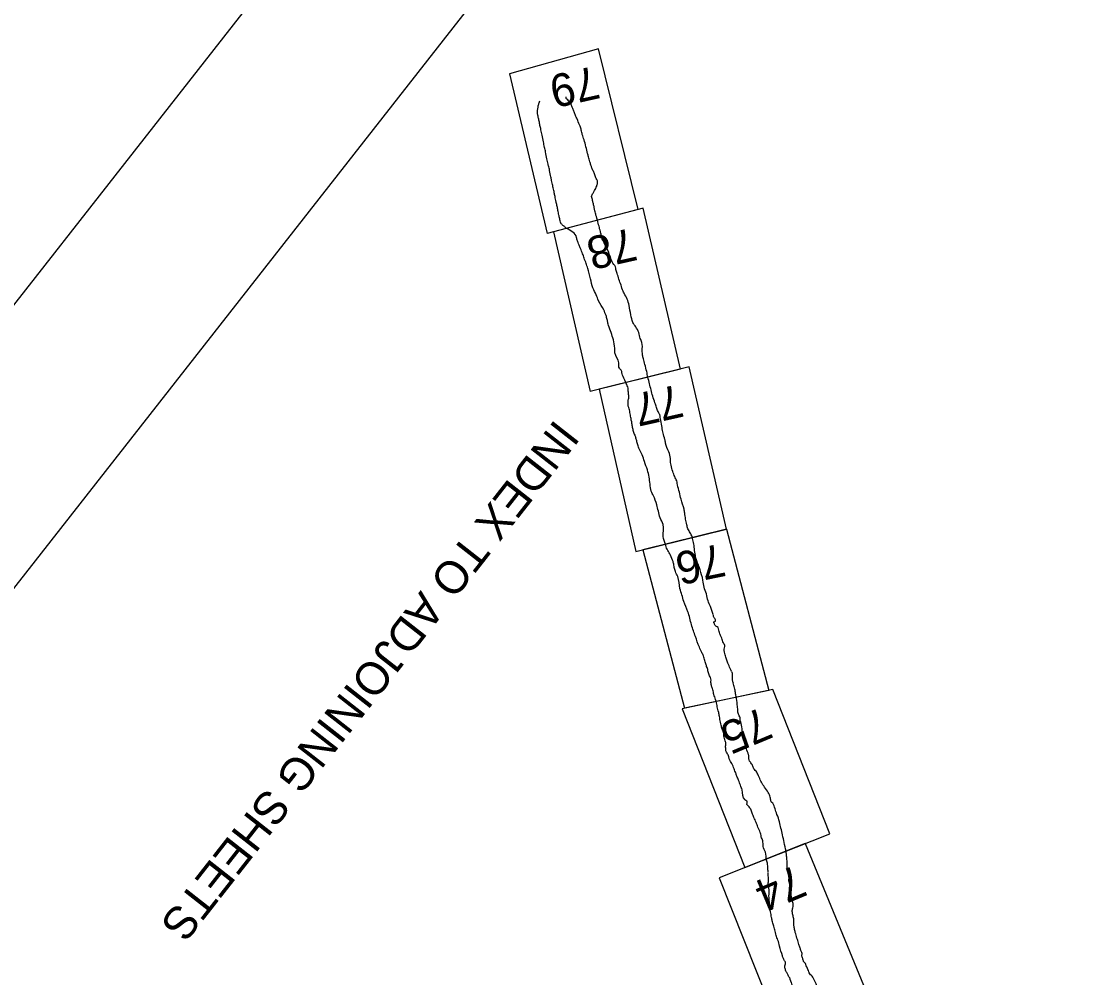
# Model space of a CAD drawing. Extents: x 3896831 to 3918110, y 171006 to 193349.
# Drawn here: x 3900688 to 3902596, y 182098 to 183807 of the extents above; entities that cross this region are included whole.
import ezdxf

# ---------------------------------------------------------------- set-up
doc = ezdxf.new("R2010")
doc.units = 0
for name, color, linetype in [('G-ANNO-NPLT', 7, 'Continuous'), ('V-ANNO-NPLT', 7, 'Continuous'), ('V-ANNO-SYMB', 7, 'Continuous')]:
    doc.layers.add(name, color=color, linetype=linetype)

msp = doc.modelspace()

# ---------------------------------------------------------------- linework, layer by layer
at = {"layer": 'G-ANNO-NPLT'}
msp.add_lwpolyline([(3908370.1, 193119.4), (3897060.8, 178689.9), (3906571.2, 171236.1), (3917880.5, 185665.6)], close=True, dxfattribs=at)
at = {"layer": 'V-ANNO-NPLT'}
msp.add_line((3901791, 183470.5), (3901628.5, 183427.7), dxfattribs=at)
for points in [[(3901791, 183470.5), (3901720.2, 183757.6), (3901560.9, 183713), (3901628.5, 183427.7)], [(3901866.5, 183185.2), (3901800.1, 183472.9), (3901639.4, 183430.6)], [(3901639.4, 183430.6), (3901705.1, 183145.5)], [(3901882, 183189), (3901721, 183149.4), (3901786.9, 182859.3)], [(3901948.7, 182899), (3901882, 183189)], [(3901866.5, 183185.2), (3901705.1, 183145.5)], [(3901786.9, 182859.3), (3901948.7, 182899)], [(3901948.7, 182899), (3901799.4, 182862.4)], [(3901948.7, 182899), (3902024.5, 182611)], [(3901799.4, 182862.4), (3901873.5, 182578.9)], [(3902031.6, 182612.5), (3901869.7, 182578.1), (3901981.7, 182294.3)], [(3902024.5, 182611), (3901873.5, 182578.9)], [(3902133.5, 182354.4), (3902031.6, 182612.5)], [(3901981.7, 182294.3), (3902133.5, 182354.4)], [(3902089.5, 182337), (3901935.6, 182276.1), (3902045.9, 181998.7)], [(3902089.5, 182337), (3902202.4, 182063.9)]]:
    msp.add_lwpolyline(points, dxfattribs=at)
for points in [[(3901617.1, 183613.2), (3901615.4, 183620.7), (3901613.9, 183628.3), (3901612.4, 183635.2), (3901611.8, 183639.4), (3901610.9, 183644.6), (3901611.6, 183650.3), (3901612.4, 183656), (3901613.9, 183661.2), (3901615, 183664.6)], [(3901685.9, 183621.8), (3901681.7, 183632.4), (3901678.9, 183638.5), (3901676.3, 183644.8), (3901674.1, 183650.8), (3901671.6, 183656.6), (3901669.8, 183661.4), (3901668.7, 183662.5), (3901666.5, 183664.7), (3901663.3, 183667.9), (3901662.4, 183668.9), (3901662, 183670.1), (3901662.1, 183671.9)], [(3901629.8, 183551.3), (3901627.8, 183561.1), (3901625.5, 183573.3), (3901623.7, 183581.6), (3901621.5, 183591.4), (3901619.1, 183603.5), (3901617.1, 183613.2)], [(3901700.5, 183570.7), (3901697.6, 183582.7), (3901694.2, 183595.1), (3901691.1, 183604.7), (3901689.2, 183612.2), (3901687.1, 183619.6), (3901685.9, 183621.8)], [(3901716.9, 183512.4), (3901718.3, 183517.7), (3901718.3, 183520.4), (3901716.1, 183525.7), (3901713.2, 183532.6), (3901710.8, 183538.9), (3901708.2, 183545), (3901706.4, 183549.9), (3901704.7, 183555.8), (3901702.1, 183564.8), (3901700.5, 183570.7)], [(3901644.5, 183483.9), (3901642.3, 183493.8), (3901640.9, 183500.3), (3901639.2, 183509.2), (3901637.1, 183517.4), (3901636.3, 183522.3), (3901635, 183528.7), (3901632.7, 183540.2), (3901630.5, 183548.8), (3901629.8, 183551.3)], [(3901718, 183451.5), (3901716.9, 183455.3), (3901715.5, 183460.4), (3901714.7, 183464), (3901713.5, 183468.4), (3901712.5, 183473.8), (3901710.8, 183480.9), (3901709.5, 183486.5), (3901708.7, 183490.3), (3901707.8, 183493.8), (3901710.5, 183499.9), (3901713, 183504.6), (3901715, 183508), (3901716.9, 183512.4)], [(3901662.5, 183437), (3901658.4, 183440.5), (3901654.3, 183444), (3901652.7, 183446.3), (3901650.7, 183454.1), (3901649.1, 183460.5), (3901647.5, 183469), (3901646.1, 183475.8), (3901644.6, 183483.2), (3901644.5, 183483.9)], [(3901691.7, 183391.4), (3901687.9, 183400.8), (3901685.2, 183406.8), (3901683.8, 183411.4), (3901681.4, 183417.5), (3901680.8, 183420.4), (3901662.5, 183437)], [(3901723.4, 183430.9), (3901722.1, 183435.7), (3901721, 183440.5), (3901718, 183451.5)], [(3901774.6, 183299), (3901771.5, 183310.4), (3901765.7, 183320.8), (3901763.9, 183324.4), (3901760.3, 183335.5), (3901756.6, 183345.9), (3901753.4, 183356.3), (3901751.2, 183363.3), (3901750.5, 183368.2), (3901747.4, 183372.4), (3901738.3, 183393.7), (3901729.9, 183410.8), (3901726, 183420.2), (3901725, 183424.9), (3901723.4, 183430.9)], [(3901733.6, 183281.1), (3901729.3, 183291), (3901720.2, 183307.5), (3901716, 183317.8), (3901710.2, 183330.4), (3901705.9, 183346.4), (3901700.8, 183365.3), (3901698, 183374.1), (3901694.4, 183383.5), (3901691.7, 183391.4)], [(3901806.3, 183180.7), (3901803, 183193.4), (3901800.2, 183203.7), (3901798.8, 183210.2), (3901798.3, 183217.8), (3901797.5, 183232.7), (3901794.8, 183239.8), (3901791.9, 183250.6), (3901786.7, 183260.6), (3901781.7, 183268.7), (3901777.8, 183282.1), (3901774.6, 183299)], [(3901769.6, 183159.4), (3901764.1, 183171.9), (3901762.2, 183176.6), (3901761.1, 183182.4), (3901757.4, 183186.7), (3901756.2, 183196.2), (3901749.4, 183214.2), (3901749, 183222.6), (3901746.7, 183237.8), (3901738.2, 183263.1), (3901737, 183267.6), (3901735.6, 183273.6), (3901733.6, 183281.1)], [(3901829.5, 183104), (3901826.5, 183109.6), (3901823.8, 183116.7), (3901821, 183124.8), (3901817, 183136.9), (3901811.3, 183159), (3901808.3, 183170.8), (3901806.3, 183180.9)], [(3901723, 183149.9), (3901722.8, 183149.5), (3901722.2, 183149.2), (3901721.8, 183149), (3901721.2, 183148.7)], [(3901778.8, 183092), (3901778.7, 183093.1), (3901777.4, 183100.9), (3901775.9, 183110.1), (3901775, 183114.4), (3901773.1, 183118.7), (3901773.1, 183125.8), (3901773.1, 183130.2), (3901774, 183133), (3901773.8, 183139.9), (3901773.4, 183144.3), (3901772.9, 183151.4), (3901769.6, 183159.4)], [(3901778.8, 183092), (3901779.7, 183085.1), (3901781.2, 183077.9), (3901783.3, 183071), (3901786.6, 183063.2)], [(3901887.5, 182885.2), (3901884, 182892.6), (3901880, 182899.5), (3901878, 182907.1), (3901875.8, 182917), (3901874.3, 182927.9), (3901873.1, 182934.7), (3901867.6, 182952.5), (3901864.7, 182965.2), (3901861.3, 182978.3), (3901859.1, 182987.5), (3901855.5, 182994.8), (3901852, 183005.1), (3901849.2, 183016.2), (3901848.7, 183025.5), (3901845.8, 183037.4), (3901839.8, 183052.7), (3901839.3, 183056.7), (3901838.6, 183059.5), (3901835.4, 183071), (3901833.6, 183080.6), (3901831.5, 183093.4), (3901829.5, 183104)], [(3901790.3, 183050.1), (3901788.3, 183057.2), (3901786.6, 183063.2)], [(3901839.7, 182872.2), (3901835.8, 182886), (3901835.6, 182907.6), (3901830.3, 182919.3), (3901827, 182931.6), (3901824.2, 182942.7), (3901818.1, 182958.8), (3901814.4, 182967), (3901812.2, 182979.8), (3901810.5, 182992.3), (3901807.6, 183005), (3901802, 183019.9), (3901798.3, 183031.8), (3901793.1, 183041.7), (3901790.3, 183050.1)], [(3901925.3, 182746.5), (3901920.1, 182760.9), (3901915.9, 182771), (3901912.9, 182783.3), (3901908.9, 182795.4), (3901906.7, 182807.8), (3901901.7, 182826.6), (3901899.6, 182833.1), (3901895.2, 182841.6), (3901893.2, 182852.2), (3901891.5, 182864.1), (3901889.9, 182875.2), (3901887.5, 182885.2)], [(3901904.9, 182678.5), (3901900.3, 182688.3), (3901893.3, 182707.2), (3901889.6, 182717.6), (3901886.2, 182728.5), (3901879.8, 182751.6), (3901872.5, 182769.7), (3901869.1, 182781.5), (3901865.6, 182793.2), (3901861.6, 182814.4), (3901857.5, 182823.4), (3901855.4, 182830.8), (3901854.2, 182838.3), (3901852.3, 182843.9), (3901847.5, 182855.1), (3901842.7, 182863.2), (3901839.7, 182872.2)], [(3901935.7, 182716.3), (3901932.3, 182724.5), (3901929.6, 182725.9), (3901928.8, 182726.8), (3901927.6, 182729.2), (3901926.8, 182731.1), (3901926.3, 182732.8), (3901926.5, 182733.4), (3901929, 182734.9), (3901929.3, 182735.6), (3901927, 182740.4), (3901925.1, 182746.3)], [(3901957.9, 182645), (3901955.5, 182650.3), (3901951.4, 182659.8), (3901948.6, 182666.6), (3901946.5, 182674.4), (3901945.1, 182679.5), (3901944.8, 182684.8), (3901945.6, 182689.2), (3901945.2, 182692.8), (3901943.4, 182696.1), (3901940.4, 182704.1), (3901937.9, 182709), (3901936.9, 182712.3), (3901935.7, 182716.3)], [(3901938.4, 182554), (3901936.2, 182564.4), (3901934.9, 182571.7), (3901933.4, 182576.8), (3901931.5, 182586.2), (3901928.5, 182597.1), (3901925.8, 182605.5), (3901924, 182614.2), (3901921.8, 182619.9), (3901921.1, 182626.6), (3901920.9, 182631.9), (3901917.7, 182639), (3901915.7, 182646.2), (3901913.4, 182653.7), (3901911.2, 182660), (3901908.7, 182668.6), (3901907.5, 182672.5), (3901904.9, 182678.5)], [(3901957.9, 182645), (3901959.1, 182638.7), (3901958.8, 182634.5), (3901959.1, 182629.4), (3901960.6, 182624.2)], [(3901967.9, 182589.6), (3901965.4, 182603), (3901964.2, 182611.2), (3901961.7, 182620), (3901960.6, 182624.2)], [(3902006, 182458), (3902002.8, 182464.8), (3901998, 182471), (3901995.4, 182476.7), (3901991.5, 182482.9), (3901989.2, 182486.7), (3901988.8, 182492.8), (3901988.2, 182496), (3901984.4, 182506.7), (3901982.1, 182516.6), (3901981.3, 182521.7), (3901979.4, 182528.2), (3901977.6, 182536.9), (3901976.7, 182542.5), (3901974.2, 182554.9), (3901973.1, 182558.5), (3901973, 182562.2), (3901970.1, 182568.6), (3901969.1, 182575.7), (3901968.1, 182585), (3901967.9, 182589.6)], [(3901976.9, 182433.4), (3901973.6, 182441.5), (3901970.4, 182450.4), (3901967.4, 182457.7), (3901965.4, 182463), (3901962.6, 182470.6), (3901958.2, 182480), (3901955.8, 182483.8), (3901953.9, 182488.5), (3901952.3, 182493.8), (3901948.9, 182500.6), (3901947.9, 182503.2), (3901947.4, 182507.6), (3901947, 182511.5), (3901947.9, 182514.9), (3901946.3, 182520.6), (3901945.1, 182525.2), (3901943.8, 182533.5), (3901943.1, 182537.6), (3901940.9, 182541.6), (3901939.5, 182548.6), (3901938.4, 182554)], [(3902055.3, 182323.6), (3902051.8, 182339.1), (3902049.1, 182352.7), (3902046.2, 182364.5), (3902043.7, 182376.1), (3902039.1, 182389.4), (3902035.7, 182399.3), (3902031.4, 182409.3), (3902028.8, 182412), (3902027.5, 182418.4), (3902026.5, 182422.3), (3902022, 182430.7), (3902015.4, 182440.2), (3902006, 182458)], [(3902023.4, 182286.6), (3902022.6, 182294.4), (3902022.3, 182300), (3902020.2, 182307.7), (3902018.5, 182321.6), (3902014.4, 182332), (3902013.7, 182342.1), (3902011, 182349.1), (3902010.2, 182353.9), (3902009.2, 182357.1), (3902005, 182366.5), (3902001.8, 182375.1), (3901997.9, 182383.6), (3901994.8, 182391.5), (3901992.1, 182398.4), (3901988.3, 182403.9), (3901985.2, 182408.2), (3901985.9, 182411.2), (3901985, 182413.1), (3901982.2, 182415.5), (3901976.9, 182433.4)], [(3902074.8, 182168.2), (3902071.9, 182178.5), (3902070.2, 182185.5), (3902069.2, 182192), (3902069.2, 182201.1), (3902067.9, 182207.8), (3902066.5, 182215.8), (3902067.3, 182222.4), (3902068.1, 182230.3), (3902065.5, 182236.9), (3902064.5, 182247.4), (3902062.9, 182256.6), (3902062.7, 182264.7), (3902060.7, 182268.6), (3902060.7, 182274.8), (3902057.9, 182290.1), (3902057.3, 182301.3), (3902056.6, 182310.9), (3902055.9, 182318.3), (3902055.3, 182323.6)], [(3902048.9, 182136.5), (3902043.8, 182153.8), (3902040.8, 182164.7), (3902037.5, 182173.1), (3902035.2, 182182.9), (3902033.1, 182191.4), (3902030.7, 182199), (3902029.5, 182205.1), (3902027.5, 182215.2), (3902026.2, 182228.2), (3902024.8, 182244), (3902025, 182254.6), (3902023.6, 182265.4), (3902023.8, 182272.6), (3902023.4, 182281.9), (3902023.4, 182285.4)], [(3902126.6, 182053.6), (3902123.5, 182059), (3902120.3, 182064.9), (3902115.5, 182072.2), (3902111.8, 182079.8), (3902108, 182089), (3902105.7, 182093.7), (3902103.2, 182098.6), (3902097.9, 182104.2), (3902094.5, 182112.2), (3902091.5, 182118.8), (3902089.8, 182123.1), (3902086.8, 182126.4), (3902085.2, 182131.9), (3902083.4, 182137.1), (3902083.9, 182139.5), (3902082.3, 182145), (3902080.5, 182150.3), (3902078.3, 182156.8), (3902077, 182161.6), (3902075.8, 182165.8), (3902074.8, 182168.2)], [(3902061.2, 182097.5), (3902060.4, 182099.1), (3902057.8, 182104.5), (3902055.2, 182109.4), (3902053.3, 182115.2), (3902053, 182118.8), (3902054.4, 182122.3), (3902052.8, 182127.8), (3902050.6, 182131.5), (3902048.9, 182136.5)], [(3902061.2, 182097.5), (3902065.2, 182086.3), (3902068.7, 182077.3), (3902075.7, 182065.6)]]:
    msp.add_spline(points, degree=3, dxfattribs=at)
at = {"layer": 'V-ANNO-SYMB'}
msp.add_lwpolyline([(3907767.9, 191844.4), (3897563.8, 178825.1), (3906582.3, 171756.8), (3916786.3, 184776.1), (3907767.9, 191844.4)], dxfattribs=at)

# ---------------------------------------------------------------- texts
at = {"layer": 'V-ANNO-NPLT'}
for s, height, rotation, p in [('79', 58.5, 192.624, (3901713.5, 183727.5)), ('78', 58.5, 192.624, (3901780.1, 183438.1)), ('77', 58.5, 192.624, (3901863.1, 183158.3)), ('INDEX TO ADJOINING SHEETS', 58.33, 231.9121, (3901643.1, 183097.6)), ('76', 58.5, 191.624, (3901939.2, 182873.6)), ('75', 58.5, 202.624, (3902013.2, 182582.5)), ('74', 58.5, 202.624, (3902074.2, 182300.5))]:
    msp.add_text(s, height=height, rotation=rotation, dxfattribs=at).set_placement(p)

doc.saveas('drawing.dxf')
